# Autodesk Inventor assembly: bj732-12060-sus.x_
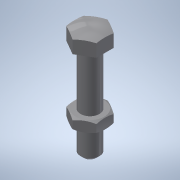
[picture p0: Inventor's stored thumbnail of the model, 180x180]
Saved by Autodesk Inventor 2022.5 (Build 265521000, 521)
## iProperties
Part Number: bj732-12060-sus.x_
Material: 一般
Document SubType Name: Assembly
Designer: ImaoCorp
Sending System: SOLIDWORKS 2017-2017317
MC: AMD64
MC_MODEL: Intel64 Family 6 Model 60 Stepping 3, GenuineIntel
OS: Windows_NT
FRU: Parasolid Version 29.0, build 201,  4-17-2017
FORMAT: text
GUISE: transmit
KEY: bj732-12060-sus
FILE: bj732-12060-sus.x_t
DATE: Fri Mar 15 10:10:29 2019
Author: ImaoCorp
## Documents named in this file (3)
- X:\14_SW2022-Inv2022\00_全2023-1023新製品(TCC)まで\b\bj732-12060-sus\BJ732-12060-SUS.iam
- X:\14_SW2022-Inv2022\00_全2023-1023新製品(TCC)まで\b\bj732-12060-sus\bj732-12060-sus_01.ipt
- X:\14_SW2022-Inv2022\00_全2023-1023新製品(TCC)まで\b\bj732-12060-sus\bj732-12060-sus_02.ipt
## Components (2 placed, 2 different names)
1. bj732-12060-sus_01
2. bj732-12060-sus_02
